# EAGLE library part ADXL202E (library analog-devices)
Low-Cost +-2 g Dual-Axis Accelerometer with Duty Cycle Output Source: www.analog.com/UploadedFiles/Data_Sheets/53728567227477ADXL202E_a.pdf
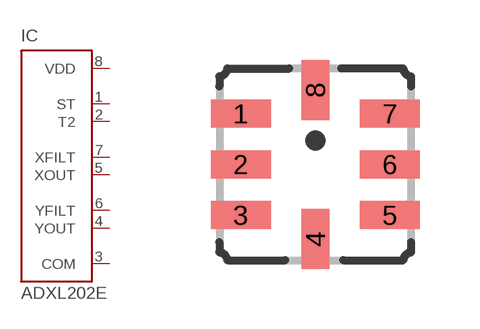
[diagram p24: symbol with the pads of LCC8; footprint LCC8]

Designator prefix IC

## ADXL202E (MF: ALTERA CORPORATION; MPN: ADXL202JE; OC_FARNELL: 1424583; OC_NEWARK: 23C7726)  [LCC8]
1  ST  in
2  T2  in
3  COM  in
4  YOUT  in
5  XOUT  in
6  YFILT  in
7  XFILT  in
8  VDD  in

## Footprint LCC8 (pad centres in mm)
8-Terminal Ceramic Leadless Chip Carrier [LCC] (E-8) Source: www.analog.com/UploadedFiles/Packages/189346426E_8.pdf
smd 1.5 x 0.7: 1 -1.867,1.27; 2 -1.867,0; 3 -1.867,-1.27; 5 1.867,-1.27; 6 1.867,0; 7 1.867,1.27
smd 0.7 x 1.5: 4 0,-1.867; 8 0,1.867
